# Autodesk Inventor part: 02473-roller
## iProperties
Author: Administrator
Shininess: 64.0
Angle Display Precision: 2
Document Length Units: 11272
Document Angle Units: 11286
Document Time Units: 11279
Document Mass Units: 11290
Document Length Units Precision: 3
Document Angle Units Precision: 2
Compacted: True
PropertySet Name: _Private Model Information
Created: 2002-04
Part Number: 02473-roller
Material: Stainless Steel, 440C
Document SubType Name: Modeling
Designer: Administrator
Control State: 0
Master: False
Checked Out: False
PropertySet Name: Design Tracking Control
Density: 0.0
Volumn: 0.0
Area: 0.0
PropertySet Name: Model Information
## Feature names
1. Revolution1
